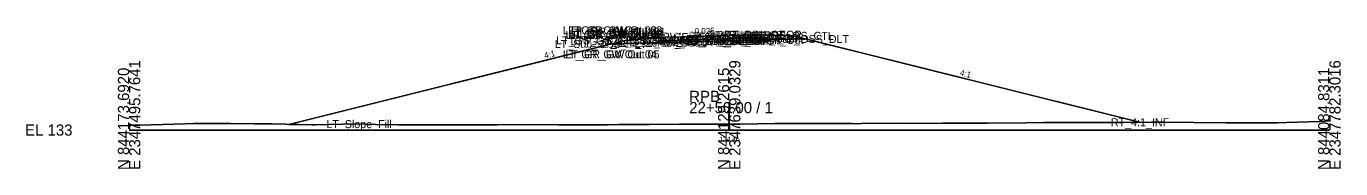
# Model space of a CAD drawing. Extents: x -76 to 2347760, y -10 to 844216.
# Drawn here: x -75.7 to 252.8, y 7490.3 to 7526 of the extents above; entities that cross this region are included whole.
import ezdxf

# ---------------------------------------------------------------- set-up
doc = ezdxf.new("R2010")
doc.units = 0
for name, color, linetype in [('Default', 7, 'Continuous'), ('Exist Cross Section Cell', 7, 'Continuous'), ('Exist XS Center Line Elevation Label', 7, 'Continuous'), ('Exist XS Ground Line', 7, 'Continuous'), ('Prop CMT Pvmt Course 1', 7, 'Continuous'), ('Prop CMT Pvmt Course 2', 7, 'Continuous'), ('Prop CMT Pvmt Course 3', 7, 'Continuous'), ('Prop CMT Pvmt Surface', 7, 'Continuous'), ('Prop CMT Pvmt Surface Shoulder', 7, 'Continuous'), ('Prop CMT Shld Paved Course 1', 7, 'Continuous'), ('Prop CMT Shld Paved Course 2', 7, 'Continuous'), ('Prop CMT Shld Paved Course 3', 7, 'Continuous'), ('Prop CMT Slope Grass', 7, 'Continuous'), ('Prop CMT Subgrade Earthwork', 7, 'Continuous'), ('Prop XS Earthwork Shape', 7, 'Continuous'), ('Prop XS SE Text', 7, 'Continuous'), ('Prop XS Side Slope Text', 7, 'Continuous'), ('Scratch_Level_0', 7, 'Continuous')]:
    doc.layers.add(name, color=color, linetype=linetype)

msp = doc.modelspace()

# ---------------------------------------------------------------- linework, layer by layer
at = {"layer": 'Exist Cross Section Cell'}
for p, q in [((100, 7500), (100, 7507.01)), ((-50, 7500), (100, 7500)), ((100, 7500), (250, 7500))]:
    msp.add_line(p, q, dxfattribs=at)
at = {"layer": 'Exist XS Ground Line'}
msp.add_lwpolyline([(-50, 7501.2), (-47.29, 7501.19), (-35.98, 7501.59), (-33.86, 7501.67), (-24.69, 7501.6), (-18.68, 7501.54), (-14.22, 7501.52), (-4.28, 7501.29), (-3.51, 7501.29), (6.72, 7501.55), (11.67, 7501.36), (17.19, 7501.28), (26.85, 7501.32), (27.66, 7501.31), (29.48, 7501.31), (38.13, 7501.28), (42.02, 7501.3), (48.6, 7501.35), (57.2, 7501.3), (59.07, 7501.29), (63.25, 7501.32), (69.54, 7501.34), (72.38, 7501.35), (80.01, 7501.39), (87.55, 7501.46), (90.48, 7501.48), (97.01, 7501.46), (100, 7501.46), (100.96, 7501.46), (102.73, 7501.48), (111.43, 7501.61), (117.91, 7501.64), (121.9, 7501.63), (130.77, 7501.6), (132.37, 7501.59), (133.08, 7501.61), (142.84, 7501.71), (148.26, 7501.67), (153.31, 7501.69), (163.44, 7501.71), (163.78, 7501.71), (164.53, 7501.72), (174.25, 7501.81), (178.61, 7501.86), (184.72, 7501.85), (193.79, 7501.89), (195.19, 7501.91), (198.29, 7501.92), (205.66, 7501.95), (208.97, 7501.94), (216.13, 7501.91), (224.14, 7501.81), (226.6, 7501.8), (232.05, 7501.78), (237.07, 7501.79), (239.32, 7501.89), (247.54, 7502.16), (250, 7502.34)], dxfattribs=at)
at = {"layer": 'Prop CMT Pvmt Course 1'}
for p, q in [((100, 7523.65), (88, 7523.35)), ((100, 7523.65), (104, 7523.75)), ((100, 7522.81), (100, 7523.65)), ((100, 7523.65), (100, 7523.65)), ((100, 7523.65), (100, 7522.81)), ((100, 7522.81), (100, 7523.65)), ((100, 7522.81), (100, 7523.65)), ((100, 7523.65), (100, 7523.65)), ((100, 7523.65), (100, 7522.81)), ((100, 7522.81), (100, 7523.65)), ((104, 7523.75), (104, 7522.91)), ((88, 7523.35), (88, 7522.51)), ((88, 7522.51), (100, 7522.81)), ((104, 7522.91), (100, 7522.81)), ((100, 7522.81), (100, 7522.81)), ((100, 7522.81), (100, 7522.81))]:
    msp.add_line(p, q, dxfattribs=at)
at = {"layer": 'Prop CMT Pvmt Course 2'}
for p, q in [((88, 7522.51), (100, 7522.81)), ((100, 7522.81), (88, 7522.51)), ((88, 7522.51), (88, 7522.51)), ((104, 7522.91), (100, 7522.81)), ((100, 7522.81), (104, 7522.91)), ((100, 7522.81), (100, 7522.81)), ((100, 7522.81), (100, 7522.81)), ((104, 7522.91), (104, 7522.91))]:
    msp.add_line(p, q, dxfattribs=at)
at = {"layer": 'Prop CMT Pvmt Course 3'}
for p, q in [((100, 7522.81), (88, 7522.51)), ((88, 7522.51), (88, 7522.01)), ((88, 7522.01), (100, 7522.31)), ((100, 7522.81), (104, 7522.91)), ((100, 7522.31), (100, 7522.81)), ((100, 7522.31), (100, 7522.81)), ((104, 7522.41), (100, 7522.31)), ((104, 7522.91), (104, 7522.41))]:
    msp.add_line(p, q, dxfattribs=at)
at = {"layer": 'Prop CMT Pvmt Surface'}
for q in [(88, 7523.35), (104, 7523.75)]:
    msp.add_line((100, 7523.65), q, dxfattribs=at)
at = {"layer": 'Prop CMT Pvmt Surface Shoulder'}
for p, q in [((104, 7523.75), (108, 7523.85)), ((88, 7523.35), (84, 7523.25))]:
    msp.add_line(p, q, dxfattribs=at)
at = {"layer": 'Prop CMT Shld Paved Course 1'}
for p, q in [((104, 7523.75), (108, 7523.85)), ((104, 7522.91), (104, 7523.75)), ((108, 7523.85), (108, 7523.01)), ((88, 7523.35), (84, 7523.25)), ((84, 7523.25), (84, 7522.41)), ((84, 7522.41), (88, 7522.51)), ((88, 7522.51), (88, 7523.35)), ((108, 7523.01), (104, 7522.91))]:
    msp.add_line(p, q, dxfattribs=at)
at = {"layer": 'Prop CMT Shld Paved Course 2'}
for p, q in [((88, 7522.51), (84, 7522.41)), ((84, 7522.41), (88, 7522.51)), ((84, 7522.41), (84, 7522.41)), ((88, 7522.51), (88, 7522.51)), ((104, 7522.91), (108, 7523.01)), ((108, 7523.01), (104, 7522.91)), ((104, 7522.91), (104, 7522.91)), ((108, 7523.01), (108, 7523.01))]:
    msp.add_line(p, q, dxfattribs=at)
at = {"layer": 'Prop CMT Shld Paved Course 3'}
for p, q in [((83.5, 7522.4), (82.99, 7521.89)), ((82.99, 7521.89), (88, 7522.01)), ((84, 7522.41), (83.5, 7522.4)), ((88, 7522.51), (84, 7522.41)), ((88, 7522.01), (88, 7522.51)), ((104, 7522.91), (108, 7523.01)), ((104, 7522.41), (104, 7522.91)), ((108.99, 7522.54), (104, 7522.41)), ((108, 7523.01), (108.5, 7523.03)), ((108.5, 7523.03), (108.99, 7522.54))]:
    msp.add_line(p, q, dxfattribs=at)
at = {"layer": 'Prop CMT Slope Grass'}
for p, q in [((108, 7523.85), (116, 7523.57)), ((116, 7523.57), (202.52, 7501.94)), ((73.99, 7522.45), (-10.1, 7501.42)), ((84, 7523.25), (73.99, 7522.45))]:
    msp.add_line(p, q, dxfattribs=at)
at = {"layer": 'Prop CMT Subgrade Earthwork'}
for p, q in [((82.99, 7521.89), (70.51, 7521.58)), ((88, 7522.01), (82.99, 7521.89)), ((100, 7522.31), (88, 7522.01)), ((100, 7522.31), (104, 7522.41)), ((104, 7522.41), (108.99, 7522.54)), ((108.99, 7522.54), (119.1, 7522.79))]:
    msp.add_line(p, q, dxfattribs=at)
at = {"layer": 'Prop XS Earthwork Shape'}
msp.add_lwpolyline([(184.72, 7501.85), (193.79, 7501.89), (195.19, 7501.91), (198.29, 7501.92), (202.52, 7501.94), (119.1, 7522.79), (108.99, 7522.54), (104, 7522.41), (100, 7522.31), (88, 7522.01), (82.99, 7521.89), (70.51, 7521.58), (-10.1, 7501.42), (-4.28, 7501.29), (-3.51, 7501.29), (6.72, 7501.55), (11.67, 7501.36), (17.19, 7501.28), (26.85, 7501.32), (27.66, 7501.31), (29.48, 7501.31), (38.13, 7501.28), (42.02, 7501.3), (48.6, 7501.35), (57.2, 7501.3), (59.07, 7501.29), (63.25, 7501.32), (69.54, 7501.34), (72.38, 7501.35), (80.01, 7501.39), (87.55, 7501.46), (90.48, 7501.48), (97.01, 7501.46), (100, 7501.46), (100.96, 7501.46), (102.73, 7501.48), (111.43, 7501.61), (117.91, 7501.64), (121.9, 7501.63), (130.77, 7501.6), (132.37, 7501.59), (133.08, 7501.61), (142.84, 7501.71), (148.26, 7501.67), (153.31, 7501.69), (163.44, 7501.71), (163.78, 7501.71), (164.53, 7501.72), (174.25, 7501.81), (178.61, 7501.86)], close=True, dxfattribs=at)

# ---------------------------------------------------------------- texts
at = {"layer": 'Default'}
msp.add_text('-', height=0.0001, dxfattribs=at).set_placement((-50, 7500))
at = {"layer": 'Exist Cross Section Cell'}
for s, p in [('E 2347495.7641', (-47.2, 7490)), ('E 2347639.0329', (102.8, 7490)), ('E 2347782.3016', (252.8, 7490)), ('N 844173.6920', (-50, 7490)), ('N 844129.2615', (100, 7490)), ('N 844084.8311', (250, 7490))]:
    msp.add_text(s, height=2.8, rotation=90, dxfattribs=at).set_placement(p)
for s, p in [('22+50.00 / 1', (90, 7504.21)), ('RPB', (90, 7507.01)), ('EL 133', (-76, 7498.6))]:
    msp.add_text(s, height=2.8, dxfattribs=at).set_placement(p)
at = {"layer": 'Exist XS Center Line Elevation Label'}
msp.add_text('134.46', height=1.2, dxfattribs=at).set_placement((97.52, 7497.17))
at = {"layer": 'Prop XS SE Text'}
msp.add_text('0.025', height=1.5, rotation=1.4321, dxfattribs=at).set_placement((91.38, 7523.98))
at = {"layer": 'Prop XS Side Slope Text'}
for rotation, p in [(14.0362, (53.92, 7517.86)), (345.9638, (157.53, 7513.71))]:
    msp.add_text('4:1', height=1.5, rotation=rotation, dxfattribs=at).set_placement(p)
at = {"layer": 'Scratch_Level_0'}
for s, p in [('LT_GS_OS_GR_Face_GW', (56.75, 7521.45)), ('LT_GR_GW Out 03', (58.43, 7523.95)), ('LT_GR_GW Out 06', (59.05, 7522.78)), ('LT_GR_GW Out 02', (59.77, 7523.95)), ('LT_GR_GW Out 09', (59.77, 7523.36)), ('LT_GR_GW Out 07', (59.77, 7522.78)), ('LT_GR_GW Out 08', (60.04, 7523.07)), ('LT_GR_GW Out 01', (60.6, 7523.65)), ('LT_PS3_Shelf_Out', (69.48, 7521.4)), ('LT_PS3_OEOP', (74.24, 7521.41)), ('LT_PS2_OEOP', (74.24, 7521.41)), ('LT_PS1_OEOP', (74.8, 7522.25)), ('LT_PV3_OEOT', (78.17, 7521.51)), ('LT_PV2_OEOT', (78.17, 7521.51)), ('LT_PV1_OEOT', (78.74, 7522.35)), ('RT_Sub_OEEOP', (89.17, 7521.31)), ('LT_Sub_OEEOP', (89.21, 7521.31)), ('RT_PV2_OEEOP', (89.26, 7521.81)), ('RT_PV3_OEEOP', (89.26, 7521.81)), ('LT_PV2_OEEOP', (89.31, 7521.81)), ('LT_PV3_OEEOP', (89.31, 7521.81)), ('RT_PV1_OEEOP', (89.83, 7522.65)), ('LT_PV1_OEEOP', (89.87, 7522.65)), ('RT_PV2_IEEOP', (89.91, 7521.81)), ('LT_PV2_IEEOP', (89.95, 7521.81)), ('RT_PV1_IEEOP', (90.47, 7522.65)), ('LT_PV1_IEEOP', (90.52, 7522.65)), ('RT_Sub_Trench_Out', (93.15, 7521.54)), ('PV2_PGL', (93.91, 7521.81)), ('RT_Sub_OEOT', (94.03, 7521.41)), ('RT_PV3_OEOT', (94.13, 7521.91)), ('RT_PV2_OEOT', (94.13, 7521.91)), ('RT_PS3_Shelf_Out', (94.44, 7522.03)), ('PV1_PGL', (94.47, 7522.65)), ('RT_PV1_OEOT', (94.69, 7522.75)), ('RT_PS3_OEOP', (98.19, 7522.01)), ('RT_PS2_OEOP', (98.19, 7522.01)), ('RT_PS1_OEOP', (98.76, 7522.85)), ('RT_GS_OS_CTL', (105.32, 7522.57)), ('RT_Sub_OSS_DLT', (106.46, 7521.79)), ('LT_Sub_OSS_DLT', (56.39, 7520.54)), ('LT_GS_OS_CTL', (60.36, 7521.21)), ('LT_Sub_Trench_Out', (67.19, 7520.89)), ('LT_Sub_OEOT', (78.08, 7521.01)), ('LT_GR_GW Out 04', (58.43, 7517.95)), ('LT_GR_GW Out 05', (59.1, 7517.95)), ('LT_Slope_Fill', (-0.69, 7500.47)), ('RT_4:1_INF', (195.4, 7500.94))]:
    msp.add_text(s, height=2, dxfattribs=at).set_placement(p)

doc.saveas('drawing.dxf')
